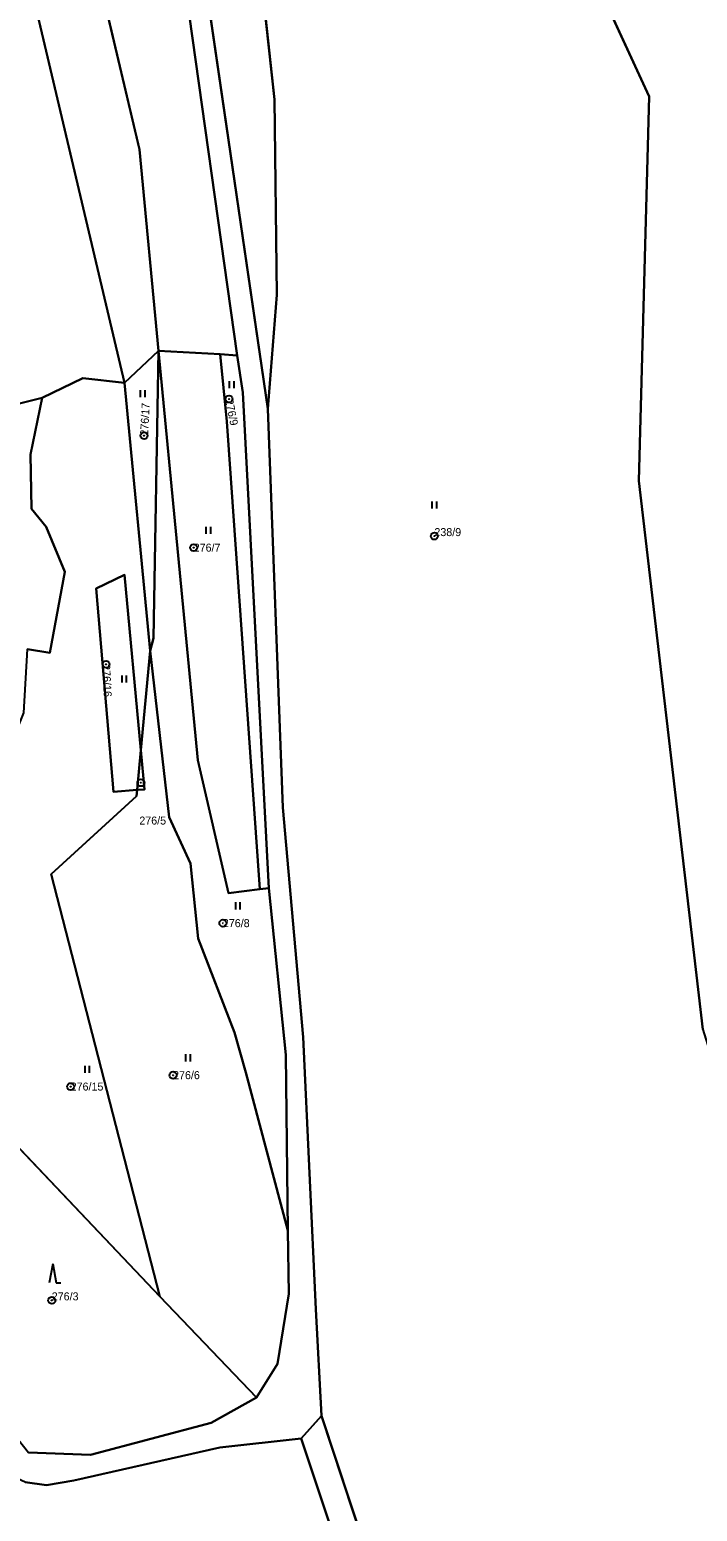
# Model space of a CAD drawing. Extents: x -652854 to -650068, y -1097661 to -1095417.
# Drawn here: x -651686.9 to -651545, y -1096801.7 to -1096486.9 of the extents above; entities that cross this region are included whole.
import ezdxf

# ---------------------------------------------------------------- set-up
doc = ezdxf.new("R2010")
doc.units = 0
for name, color, linetype in [('Definiční body parcel', 7, 'Continuous'), ('Hranice parcel', 7, 'Continuous'), ('Obvody jako plochy', 7, 'Continuous'), ('Parcelní čísla', 7, 'Continuous'), ('Prvky pro prodl_ par_ č_', 7, 'Continuous'), ('Značky kultur', 7, 'Continuous')]:
    doc.layers.add(name, color=color, linetype=linetype)

msp = doc.modelspace()

# ---------------------------------------------------------------- linework, layer by layer
at = {"layer": 'Definiční body parcel'}
for centre, radius in [((-651644.54, -1096565.36), 0.75), ((-651644.54, -1096565.36), 0.0327), ((-651662.6, -1096573.12), 0.75), ((-651662.6, -1096573.12), 0.0327), ((-651600.89, -1096594.47), 0.75), ((-651652.05, -1096596.92), 0.75), ((-651652.05, -1096596.92), 0.0327), ((-651600.89, -1096594.47), 0.0327), ((-651670.69, -1096621.7), 0.75), ((-651670.69, -1096621.7), 0.0327), ((-651663.28, -1096646.88), 0.75), ((-651663.28, -1096646.88), 0.0327), ((-651645.85, -1096676.71), 0.75), ((-651645.85, -1096676.71), 0.0327), ((-651656.43, -1096709.01), 0.75), ((-651656.43, -1096709.01), 0.0327), ((-651678.2, -1096711.43), 0.75), ((-651678.2, -1096711.43), 0.0327), ((-651682.22, -1096756.86), 0.75), ((-651682.22, -1096756.86), 0.0327)]:
    msp.add_circle(centre, radius, dxfattribs=at)
at = {"layer": 'Hranice parcel'}
for p, q in [((-651555.25, -1096501.03), (-651600.66, -1096402.57)), ((-651663.59, -1096512.32), (-651685.67, -1096418.62)), ((-651666.79, -1096561.93), (-651691.55, -1096456.85)), ((-651634.91, -1096501.67), (-651639.25, -1096460.97)), ((-651654.35, -1096474.04), (-651642.8, -1096556.06)), ((-651650.01, -1096473.52), (-651636.3, -1096567.46)), ((-651634.35, -1096543.17), (-651634.91, -1096501.67)), ((-651557.41, -1096582.71), (-651555.25, -1096501.03)), ((-651659.51, -1096555.13), (-651663.59, -1096512.32)), ((-651636.3, -1096567.46), (-651634.35, -1096543.17)), ((-651666.79, -1096561.93), (-651659.51, -1096555.13)), ((-651659.51, -1096555.13), (-651660.61, -1096616.16)), ((-651651.14, -1096642.1), (-651659.51, -1096555.13)), ((-651659.51, -1096555.13), (-651646.41, -1096555.8)), ((-651646.41, -1096555.8), (-651642.8, -1096556.06)), ((-651646.41, -1096555.8), (-651645.03, -1096570.12)), ((-651642.8, -1096556.06), (-651641.61, -1096563.95)), ((-651684.26, -1096565.06), (-651675.59, -1096560.88)), ((-651675.59, -1096560.88), (-651666.79, -1096561.93)), ((-651666.79, -1096561.93), (-651661.32, -1096618.82)), ((-651698.58, -1096568.61), (-651684.26, -1096565.06)), ((-651686.72, -1096577.16), (-651684.26, -1096565.06)), ((-651641.61, -1096563.95), (-651636.1, -1096669.26)), ((-651633.08, -1096652.14), (-651636.3, -1096567.46)), ((-651645.03, -1096570.12), (-651637.98, -1096669.47)), ((-651686.54, -1096588.66), (-651686.72, -1096577.16)), ((-651543.84, -1096699.33), (-651557.41, -1096582.71)), ((-651683.38, -1096592.51), (-651686.54, -1096588.66)), ((-651679.45, -1096602.03), (-651683.38, -1096592.51)), ((-651682.65, -1096619.29), (-651679.45, -1096602.03)), ((-651672.78, -1096605.61), (-651666.74, -1096602.68)), ((-651666.74, -1096602.68), (-651663.3, -1096639.97)), ((-651669.12, -1096648.83), (-651672.78, -1096605.61)), ((-651687.36, -1096618.51), (-651682.65, -1096619.29)), ((-651661.32, -1096618.82), (-651663.3, -1096639.97)), ((-651660.61, -1096616.16), (-651661.32, -1096618.82)), ((-651661.32, -1096618.82), (-651657.27, -1096654.2)), ((-651663.3, -1096639.97), (-651664.09, -1096648.41)), ((-651663.3, -1096639.97), (-651662.53, -1096648.28)), ((-651644.63, -1096670.36), (-651651.14, -1096642.1)), ((-651664.21, -1096649.73), (-651682.32, -1096666.33)), ((-651664.09, -1096648.41), (-651669.12, -1096648.83)), ((-651664.09, -1096648.41), (-651664.21, -1096649.73)), ((-651662.53, -1096648.28), (-651664.09, -1096648.41)), ((-651628.75, -1096700.93), (-651633.08, -1096652.14)), ((-651657.27, -1096654.2), (-651652.73, -1096664.05)), ((-651652.73, -1096664.05), (-651651.09, -1096679.99)), ((-651682.32, -1096666.33), (-651659.24, -1096756.04)), ((-651637.98, -1096669.47), (-651636.1, -1096669.26)), ((-651636.1, -1096669.26), (-651632.48, -1096704.72)), ((-651637.98, -1096669.47), (-651644.63, -1096670.36)), ((-651651.09, -1096679.99), (-651643.4, -1096699.97)), ((-651643.4, -1096699.97), (-651640.98, -1096708.44)), ((-651626.1, -1096758.74), (-651628.75, -1096700.93)), ((-651632.48, -1096704.72), (-651632.02, -1096742.04)), ((-651640.98, -1096708.44), (-651632.02, -1096742.04)), ((-651659.24, -1096756.04), (-651698.39, -1096714.91)), ((-651632.02, -1096742.04), (-651631.86, -1096755.44)), ((-651659.24, -1096756.04), (-651638.72, -1096777.47)), ((-651631.86, -1096755.44), (-651634.21, -1096770.32)), ((-651624.86, -1096781.39), (-651626.1, -1096758.74)), ((-651634.21, -1096770.32), (-651638.72, -1096777.47)), ((-651638.72, -1096777.47), (-651648.36, -1096782.9)), ((-651629.22, -1096786.22), (-651624.86, -1096781.39)), ((-651597.32, -1096864.7), (-651624.86, -1096781.39)), ((-651648.36, -1096782.9), (-651673.99, -1096789.65)), ((-651646.53, -1096788.1), (-651677.51, -1096795.13)), ((-651646.53, -1096788.1), (-651629.22, -1096786.22)), ((-651629.22, -1096786.22), (-651602.28, -1096866.9)), ((-651673.99, -1096789.65), (-651687.13, -1096789.17)), ((-651683.33, -1096796.11), (-651677.51, -1096795.13)), ((-651687.84, -1096795.48), (-651683.33, -1096796.11))]:
    msp.add_line(p, q, dxfattribs=at)
at = {"layer": 'Obvody jako plochy'}
for points in [[(-651659.51, -1096555.13), (-651646.41, -1096555.8), (-651642.8, -1096556.06), (-651654.35, -1096474.04), (-651659.12, -1096440.24), (-651667.53, -1096383.22), (-651669.61, -1096344.23), (-651673.04, -1096319.05), (-651710.67, -1096323.58), (-651775.7, -1096331.44), (-651785.42, -1096405.64), (-651685.67, -1096418.62), (-651663.59, -1096512.32)], [(-651663.46, -1096380.62), (-651659.4, -1096410.34), (-651650.01, -1096473.52), (-651636.3, -1096567.46), (-651634.35, -1096543.17), (-651634.91, -1096501.67), (-651639.25, -1096460.97), (-651646.4, -1096428.72), (-651658.71, -1096400.88), (-651661.63, -1096368.34), (-651664.09, -1096349.66)], [(-651659.51, -1096555.13), (-651663.59, -1096512.32), (-651685.67, -1096418.62), (-651785.42, -1096405.64), (-651788.76, -1096431.88), (-651795.6, -1096461.91), (-651799.02, -1096481.47), (-651796.23, -1096492.24), (-651783.44, -1096503.05), (-651773.01, -1096517.88), (-651753.12, -1096532.75), (-651747.93, -1096435.93), (-651691.55, -1096456.85), (-651666.79, -1096561.93)], [(-651753.12, -1096532.75), (-651718.02, -1096559.55), (-651698.58, -1096568.61), (-651684.26, -1096565.06), (-651675.59, -1096560.88), (-651666.79, -1096561.93), (-651691.55, -1096456.85), (-651747.93, -1096435.93)], [(-651753.12, -1096532.75), (-651759.68, -1096537.2), (-651724.11, -1096591.33), (-651692.16, -1096654.67), (-651691.07, -1096650.8), (-651692.81, -1096643.66), (-651688.18, -1096632.03), (-651687.36, -1096618.51), (-651682.65, -1096619.29), (-651679.45, -1096602.03), (-651683.38, -1096592.51), (-651686.54, -1096588.66), (-651686.72, -1096577.16), (-651684.26, -1096565.06), (-651698.58, -1096568.61), (-651718.02, -1096559.55)], [(-651659.51, -1096555.13), (-651666.79, -1096561.93), (-651661.32, -1096618.82), (-651660.61, -1096616.16)], [(-651632.48, -1096704.72), (-651636.1, -1096669.26), (-651637.98, -1096669.47), (-651644.63, -1096670.36), (-651651.14, -1096642.1), (-651659.51, -1096555.13), (-651660.61, -1096616.16), (-651661.32, -1096618.82), (-651657.27, -1096654.2), (-651652.73, -1096664.05), (-651651.09, -1096679.99), (-651643.4, -1096699.97), (-651640.98, -1096708.44), (-651632.02, -1096742.04)], [(-651644.63, -1096670.36), (-651637.98, -1096669.47), (-651645.03, -1096570.12), (-651646.41, -1096555.8), (-651659.51, -1096555.13), (-651651.14, -1096642.1)], [(-651642.8, -1096556.06), (-651646.41, -1096555.8), (-651645.03, -1096570.12), (-651637.98, -1096669.47), (-651636.1, -1096669.26), (-651641.61, -1096563.95)], [(-651663.3, -1096639.97), (-651666.74, -1096602.68), (-651672.78, -1096605.61), (-651669.12, -1096648.83), (-651664.09, -1096648.41)], [(-651631.86, -1096755.44), (-651632.02, -1096742.04), (-651640.98, -1096708.44), (-651643.4, -1096699.97), (-651651.09, -1096679.99), (-651652.73, -1096664.05), (-651657.27, -1096654.2), (-651661.32, -1096618.82), (-651663.3, -1096639.97), (-651662.53, -1096648.28), (-651664.09, -1096648.41), (-651664.21, -1096649.73), (-651682.32, -1096666.33), (-651659.24, -1096756.04), (-651638.72, -1096777.47), (-651634.21, -1096770.32)], [(-651663.3, -1096639.97), (-651664.09, -1096648.41), (-651662.53, -1096648.28)], [(-651716.57, -1096752.04), (-651687.13, -1096789.17), (-651673.99, -1096789.65), (-651648.36, -1096782.9), (-651638.72, -1096777.47), (-651659.24, -1096756.04), (-651698.39, -1096714.91), (-651704.69, -1096728.29), (-651708.37, -1096744.51)]]:
    msp.add_lwpolyline(points, close=True, dxfattribs=at)
for points in [[(-651600.66, -1096402.57), (-651555.25, -1096501.03), (-651557.41, -1096582.71), (-651543.84, -1096699.33), (-651522.08, -1096769.05), (-651518.41, -1096775.28), (-651435.11, -1096707.84), (-651313.19, -1096610.07), (-651245.37, -1096547.21)], [(-651543.84, -1096699.33), (-651557.41, -1096582.71), (-651555.25, -1096501.03), (-651600.66, -1096402.57)], [(-651639.25, -1096460.97), (-651634.91, -1096501.67), (-651634.35, -1096543.17), (-651636.3, -1096567.46), (-651633.08, -1096652.14), (-651628.75, -1096700.93), (-651626.1, -1096758.74), (-651624.86, -1096781.39), (-651597.32, -1096864.7), (-651593.1, -1096900.22), (-651579.58, -1096969.71), (-651571.24, -1096967.06), (-651562.74, -1096988.5), (-651533.92, -1097012.29)], [(-651687.84, -1096795.48), (-651683.33, -1096796.11), (-651677.51, -1096795.13), (-651646.53, -1096788.1), (-651629.22, -1096786.22), (-651624.86, -1096781.39), (-651626.1, -1096758.74), (-651628.75, -1096700.93), (-651633.08, -1096652.14), (-651636.3, -1096567.46), (-651650.01, -1096473.52)], [(-651654.35, -1096474.04), (-651642.8, -1096556.06), (-651641.61, -1096563.95), (-651636.1, -1096669.26), (-651632.48, -1096704.72), (-651632.02, -1096742.04), (-651631.86, -1096755.44), (-651634.21, -1096770.32), (-651638.72, -1096777.47), (-651648.36, -1096782.9), (-651673.99, -1096789.65), (-651687.13, -1096789.17)], [(-651698.39, -1096714.91), (-651659.24, -1096756.04), (-651682.32, -1096666.33), (-651664.21, -1096649.73), (-651664.09, -1096648.41), (-651669.12, -1096648.83), (-651672.78, -1096605.61), (-651666.74, -1096602.68), (-651663.3, -1096639.97), (-651661.32, -1096618.82), (-651666.79, -1096561.93), (-651675.59, -1096560.88), (-651684.26, -1096565.06), (-651686.72, -1096577.16), (-651686.54, -1096588.66), (-651683.38, -1096592.51), (-651679.45, -1096602.03), (-651682.65, -1096619.29), (-651687.36, -1096618.51)], [(-651602.28, -1096866.9), (-651629.22, -1096786.22), (-651646.53, -1096788.1), (-651677.51, -1096795.13), (-651683.33, -1096796.11), (-651687.84, -1096795.48), (-651697.4, -1096791.19), (-651705.84, -1096785.13), (-651723.8, -1096774.2), (-651787.28, -1096744.53), (-651848.2, -1096737.25), (-651871.34, -1096780.48), (-651883.31, -1096844.19)], [(-651546.15, -1097072.72), (-651559.09, -1097034.81), (-651579.58, -1096969.71), (-651593.1, -1096900.22), (-651597.32, -1096864.7), (-651624.86, -1096781.39), (-651629.22, -1096786.22), (-651602.28, -1096866.9), (-651596.98, -1096902.08), (-651584.48, -1096971.16), (-651563.08, -1097040.57), (-651550.89, -1097076.68)]]:
    msp.add_lwpolyline(points, dxfattribs=at)
at = {"layer": 'Značky kultur'}
for p, q in [((-651644.487, -1096561.545), (-651644.487, -1096563.045)), ((-651643.465, -1096563.045), (-651643.465, -1096561.545)), ((-651663.397, -1096563.445), (-651663.397, -1096564.945)), ((-651662.375, -1096564.945), (-651662.375, -1096563.445)), ((-651601.407, -1096587.095), (-651601.407, -1096588.595)), ((-651600.385, -1096588.595), (-651600.385, -1096587.095)), ((-651649.437, -1096592.485), (-651649.437, -1096593.985)), ((-651648.415, -1096593.985), (-651648.415, -1096592.485)), ((-651667.327, -1096624.075), (-651667.327, -1096625.575)), ((-651666.305, -1096625.575), (-651666.305, -1096624.075)), ((-651643.177, -1096672.275), (-651643.177, -1096673.775)), ((-651642.155, -1096673.775), (-651642.155, -1096672.275)), ((-651675.217, -1096706.995), (-651675.217, -1096708.495)), ((-651674.195, -1096708.495), (-651674.195, -1096706.995)), ((-651653.787, -1096704.575), (-651653.787, -1096706.075)), ((-651652.765, -1096706.075), (-651652.765, -1096704.575)), ((-651682.022, -1096749.109), (-651682.755, -1096753.109)), ((-651682.022, -1096749.109), (-651681.289, -1096753.109)), ((-651681.289, -1096753.109), (-651680.289, -1096753.109))]:
    msp.add_line(p, q, dxfattribs=at)

# ---------------------------------------------------------------- texts
at = {"layer": 'Parcelní čísla'}
for s, height, rotation, p in [('276/9', 1.7, 281.493, (-651645.373, -1096565.529)), ('276/17', 1.7, 87.03, (-651661.751, -1096573.164)), ('276/16', 1.7, 273.222, (-651671.539, -1096621.748)), ('276/5', 0.1, 96.318, (-651663.23, -1096646.874))]:
    msp.add_text(s, height=height, rotation=rotation, dxfattribs=at).set_placement(p)
for s, p in [('238/9', (-651600.89, -1096594.47)), ('276/7', (-651652.05, -1096597.77)), ('276/8', (-651645.85, -1096677.56)), ('276/6', (-651656.43, -1096709.86)), ('276/15', (-651678.2, -1096712.28)), ('276/3', (-651682.22, -1096756.86))]:
    msp.add_text(s, height=1.7, dxfattribs=at).set_placement(p)
at = {"layer": 'Prvky pro prodl_ par_ č_'}
msp.add_text('276/5', height=1.7, dxfattribs=at).set_placement((-651663.61, -1096655.76))

doc.saveas('drawing.dxf')
